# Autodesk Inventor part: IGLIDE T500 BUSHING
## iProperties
Shininess: 50.0
Length Units: 11272
Angle Units: 11279
Time Units: 11290
Mass Units: 11286
Length Display Precision: 3
Angle Display Precision: 2
Part Number: IGLIDE T500 BUSHING
Document SubType Name: Modeling
Created: 2003-08
Material: Delrin, Black
Description: IGUS® IGLIDE T500 BUSHING
Designer: CM
Manufacturer: Standard
Standards Organization: Custom
Density: 10.49
Volumn: 2.304646865681294
Area: 8.437628188859923
PropertySet Name: Model Information
Control State: 0
Master: False
Checked Out: False
Author: CM
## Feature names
1. Extrusion2
2. Chamfer1
3. Chamfer2
